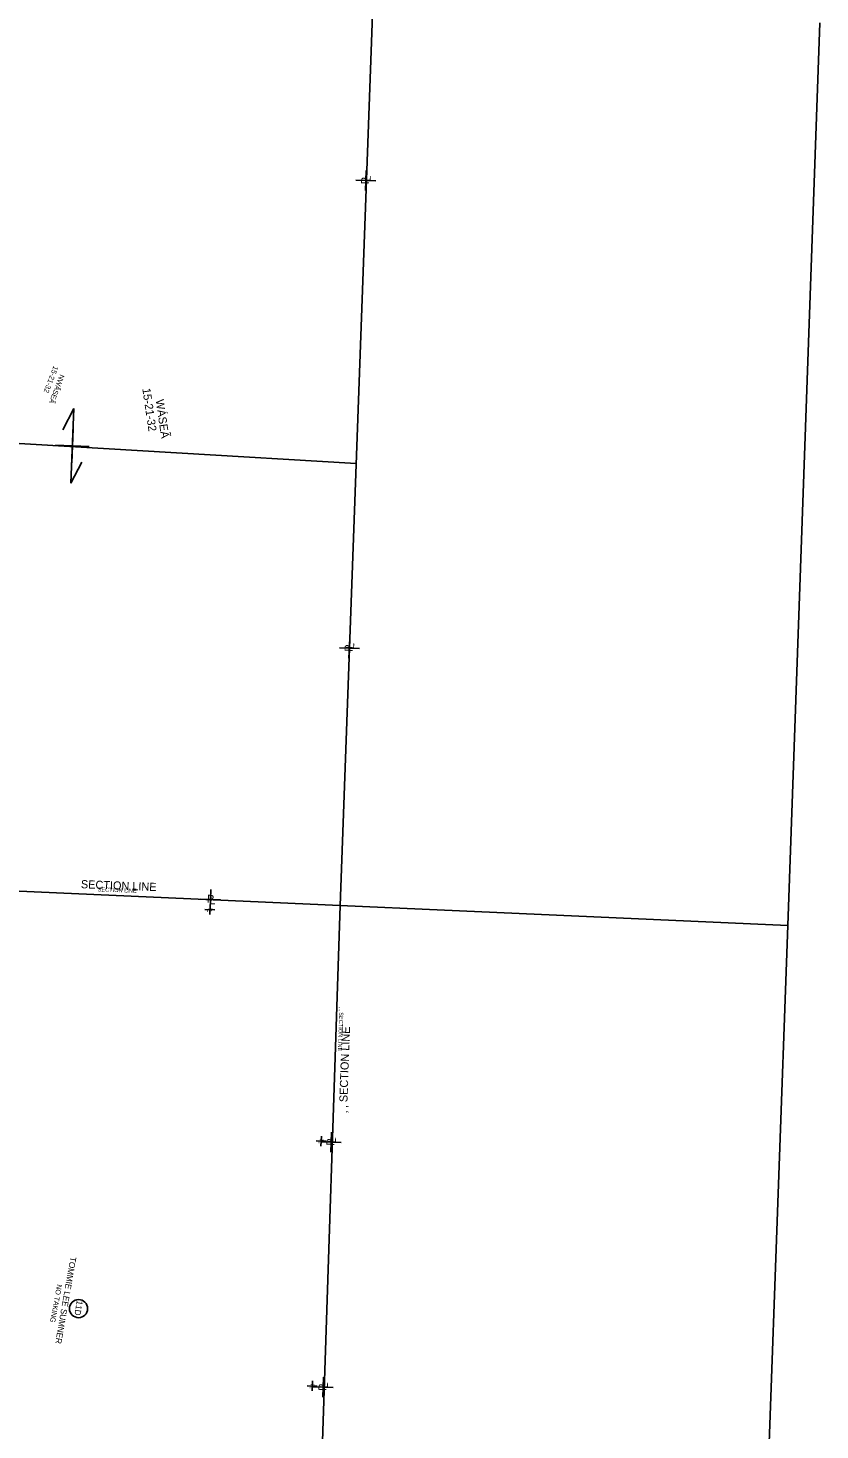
# Model space of a CAD drawing. Extents: x 2814293 to 2835768, y 121185 to 156337.
# Drawn here: x 2823907 to 2826241, y 134634 to 138763 of the extents above; entities that cross this region are included whole.
import ezdxf

# ---------------------------------------------------------------- set-up
doc = ezdxf.new("R2010")
doc.units = 0
for name, color, linetype in [('Photo-Retaining wall', 7, 'Continuous'), ('Roadway-Alignment notes', 7, 'Continuous'), ('Roadway-Ditches', 7, 'Continuous'), ('Roadway-Edge of shoulder', 7, 'Continuous'), ('Roadway-Entrances', 7, 'Continuous'), ('Roadway-Safety', 7, 'Continuous'), ('Roadway-Walls', 7, 'Continuous'), ('Scratch-2', 7, 'Continuous'), ('Scratch-5', 7, 'Continuous')]:
    doc.layers.add(name, color=color, linetype=linetype)

msp = doc.modelspace()

# ---------------------------------------------------------------- linework, layer by layer
at = {"layer": 'Roadway-Ditches'}
msp.add_circle((2824056, 134991.5), 26.7, dxfattribs=at)
at = {"layer": 'Roadway-Edge of shoulder'}
for p, q in [((2824901.9, 138284.4), (2824904, 138343.3)), ((2824873.5, 138314.9), (2824932.4, 138312.8)), ((2824853.1, 136907.7), (2824855.2, 136966.6)), ((2824824.7, 136938.2), (2824883.6, 136936.1)), ((2824446.2, 136225.9), (2824444.2, 136167)), ((2824415.8, 136197.5), (2824474.6, 136195.5)), ((2824771.2, 135483.2), (2824830.1, 135480.9)), ((2824799.5, 135452.6), (2824801.8, 135511.5)), ((2824776, 134730.6), (2824778.1, 134789.4)), ((2824747.6, 134761), (2824806.5, 134759))]:
    msp.add_line(p, q, dxfattribs=at)
at = {"layer": 'Roadway-Entrances'}
for p, q in [((2824923.2, 138830.2), (2824826.9, 136178.8)), ((2826241.2, 138778.7), (2826146.1, 136120.3)), ((2822893.1, 137598.2), (2824874.2, 137481)), ((2823507.8, 136237.3), (2826146.1, 136120.3)), ((2824826.9, 136178.8), (2824740.2, 133531.3)), ((2826146.1, 136120.3), (2826050.7, 133475.8))]:
    msp.add_line(p, q, dxfattribs=at)
at = {"layer": 'Roadway-Walls'}
for p, q in [((2824443.7, 136181.5), (2824442.6, 136152.1)), ((2824457.9, 136166.3), (2824428.4, 136167.3)), ((2824785.8, 135484.6), (2824756.3, 135485.7)), ((2824771.6, 135499.9), (2824770.5, 135470.4)), ((2824745.3, 134778.7), (2824744.3, 134749.3)), ((2824759.5, 134763.5), (2824730, 134764.5))]:
    msp.add_line(p, q, dxfattribs=at)
at = {"layer": 'Scratch-2'}
for p, q in [((2824010, 137580.1), (2824042, 137642.3)), ((2824033.5, 137422.5), (2824042, 137642.3)), ((2824039.7, 137582.4), (2824035.8, 137482.4)), ((2824087.7, 137530.5), (2823987.8, 137534.3)), ((2824037.7, 137532.4), (2824037.7, 137532.4)), ((2824065.5, 137484.7), (2824033.5, 137422.5))]:
    msp.add_line(p, q, dxfattribs=at)

# ---------------------------------------------------------------- texts
at = {"layer": 'Photo-Retaining wall'}
for s, rotation, p in [('15-21-32', 248.849, (2823982.9, 137769.4)), ('NWÃSEÃ', 248.849, (2824001.2, 137744.5)), ('NO TAKING', 259.5041, (2823992.7, 135064))]:
    msp.add_text(s, height=15, rotation=rotation, dxfattribs=at).set_placement(p)
at = {"layer": 'Roadway-Alignment notes'}
for s, p in [('15-21-32', (2824243.9, 137700.9)), ('WÁSEÃ', (2824283.2, 137667.8))]:
    msp.add_text(s, height=24, rotation=278.3561, dxfattribs=at).set_placement(p)
at = {"layer": 'Roadway-Ditches'}
for s, p in [('TOMMIE LEE SUMNER', (2824032, 135145)), ('11D', (2824051.2, 135016.4))]:
    msp.add_text(s, height=18, rotation=260.038, dxfattribs=at).set_placement(p)
at = {"layer": 'Roadway-Edge of shoulder'}
for s, rotation, p in [('L', 87.9775, (2824916.8, 138310.7)), ('P', 87.9775, (2824912.2, 138302.9)), ('P', 87.9775, (2824863.4, 136926.1)), ('L', 87.9775, (2824868, 136934)), ('P', 357.9775, (2824434.2, 136187.2)), ('L', 357.9775, (2824442, 136182.7)), ('P', 87.7804, (2824809.9, 135471)), ('L', 87.7804, (2824814.5, 135478.8)), ('P', 87.9775, (2824786.3, 134749)), ('L', 87.9775, (2824790.9, 134756.8))]:
    msp.add_text(s, height=23.6, rotation=rotation, dxfattribs=at).set_placement(p)
at = {"layer": 'Roadway-Safety'}
for s, rotation, p in [('SECTION LINE', 357.7804, (2824112.2, 136220.4)), ('‚ ‚ SECTION LINE', 267.9775, (2824825, 135881.1))]:
    msp.add_text(s, height=12, rotation=rotation, dxfattribs=at).set_placement(p)
at = {"layer": 'Roadway-Walls'}
for s, p in [('L', (2824436.2, 136168.4)), ('P', (2824438.5, 136172.3)), ('L', (2824764.2, 135486.7)), ('P', (2824766.4, 135490.7)), ('L', (2824737.9, 134765.6)), ('P', (2824740.1, 134769.5))]:
    msp.add_text(s, height=11.8, rotation=267.9775, dxfattribs=at).set_placement(p)
at = {"layer": 'Scratch-5'}
for s, rotation, p in [('SECTION LINE', 357.7804, (2824062.7, 136229.9)), ('‚ ‚ SECTION LINE', 87.9775, (2824847.3, 135567.2))]:
    msp.add_text(s, height=24, rotation=rotation, dxfattribs=at).set_placement(p)

doc.saveas('drawing.dxf')
